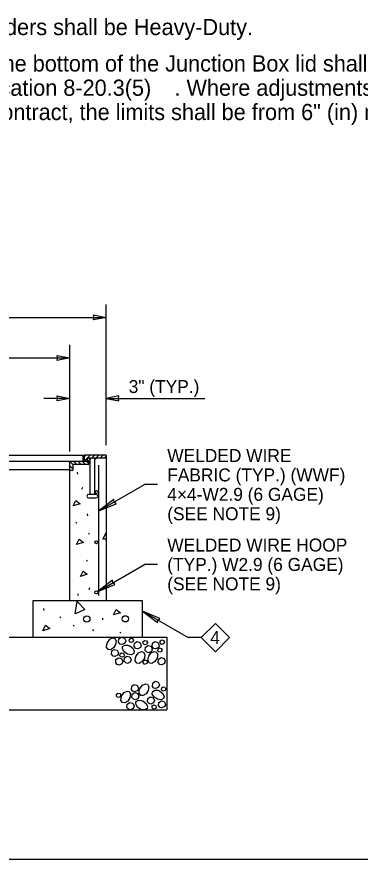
# Model space of a CAD drawing. Extents: x 99862 to 112891, y 95370 to 105076.
# Drawn here: x 102089 to 102513, y 100000 to 101040 of the extents above; entities that cross this region are included whole.
import ezdxf

# ---------------------------------------------------------------- set-up
doc = ezdxf.new("R2010")
doc.units = 0
for name, color, linetype in [('Level 1', 7, 'Continuous'), ('Level 10', 7, 'Continuous'), ('Level 12', 7, 'Continuous'), ('Level 15', 7, 'Continuous'), ('Level 2', 7, 'Continuous'), ('Level 20', 7, 'Continuous'), ('Level 3', 7, 'Continuous'), ('Level 5', 7, 'Continuous'), ('Level 6', 7, 'Continuous'), ('Level 8', 7, 'Continuous')]:
    doc.layers.add(name, color=color, linetype=linetype)

msp = doc.modelspace()

# ---------------------------------------------------------------- linework, layer by layer
at = {"layer": 'Level 1'}
for p, q in [((102199, 100498.8), (102199, 100318.8)), ((102154, 100318.8), (102154, 100480.2)), ((102244, 100318.8), (102108.6, 100318.8)), ((102108.6, 100318.8), (102108.6, 100273.8)), ((102244, 100273.8), (102244, 100318.8))]:
    msp.add_line(p, q, dxfattribs=at)
msp.add_lwpolyline([(99862, 99999.5), (103151, 99999.5), (103151, 102075.5), (99862, 102075.5)], close=True, dxfattribs=at)
at = {"layer": 'Level 10'}
msp.add_line((102190.1, 100325.2), (102190.1, 100486.4), dxfattribs=at)
for centre, radius in [((102187.2, 100453), 1.88), ((102187, 100391.1), 1.88), ((102186.9, 100329.2), 1.88), ((102175.1, 100296.3), 3.9), ((102222.7, 100296.4), 3.9)]:
    msp.add_circle(centre, radius, dxfattribs=at)
at = {"layer": 'Level 12'}
for p, q in [((102163.3, 100477.7), (102163.6, 100475.3)), ((102169.1, 100456.8), (102170.2, 100459.2)), ((102175.7, 100426.2), (102176, 100423.8)), ((102161.7, 100416), (102162.7, 100414.4)), ((102177, 100402.6), (102178.1, 100401)), ((102174.6, 100369.3), (102175.6, 100367.7)), ((102177.8, 100332.7), (102178.9, 100335)), ((102163.9, 100327.5), (102164.2, 100325.1)), ((102121.6, 100309.3), (102121.9, 100306.9)), ((102141.6, 100299.3), (102142.7, 100297.7)), ((102158.2, 100288.8), (102159.2, 100287.2)), ((102194.3, 100297.4), (102194.6, 100295)), ((102182.3, 100283.3), (102183.4, 100281.7)), ((102215.7, 100280.1), (102216.7, 100278.5)), ((102227.1, 100273.8), (102227.1, 100273.8))]:
    msp.add_line(p, q, dxfattribs=at)
for points in [[(102158.4, 100435.9), (102161.6, 100442.5), (102167, 100438.5), (102158.4, 100435.9)], [(102194.9, 100394.7), (102199, 100402.5)], [(102162.3, 100388.1), (102165.5, 100394.8), (102170.8, 100390.8), (102162.3, 100388.1)], [(102199, 100395), (102195.2, 100394.7)], [(102167.2, 100348.7), (102170.4, 100355.4), (102175.7, 100351.4), (102167.2, 100348.7)], [(102160.8, 100302.4), (102163, 100317.7)], [(102163, 100317.7), (102172.5, 100307.8), (102161.1, 100302.5)], [(102208, 100301.3), (102211.2, 100307.9), (102216.5, 100304), (102208, 100301.3)], [(102120.9, 100281.7), (102124.1, 100288.4), (102129.4, 100284.4), (102120.9, 100281.7)], [(102200.6, 100267.3), (102203.5, 100271.1), (102207.2, 100272.8), (102209.8, 100272.2), (102211.4, 100269.3), (102210.7, 100264.6), (102207.9, 100260.4), (102204.3, 100258.2), (102201.3, 100258.4), (102199.5, 100261.3), (102199.6, 100264.9), (102200.7, 100267.5)], [(102214.4, 100267.5), (102214.8, 100271.6), (102217.9, 100273.6), (102221.6, 100272.6), (102223.2, 100269.1), (102222.1, 100266.3), (102218.7, 100264.6), (102216.4, 100265.2), (102214.4, 100267.5)], [(102227.5, 100268.9), (102227.7, 100271.4), (102229.6, 100272.6), (102231.8, 100272), (102232.8, 100269.9), (102232.1, 100268.2), (102230.1, 100267.2), (102228.7, 100267.6), (102227.5, 100268.9)], [(102233.5, 100262.2), (102233.9, 100266.3), (102237.1, 100268.3), (102240.7, 100267.3), (102242.3, 100263.8), (102241.2, 100260.9), (102237.9, 100259.3), (102235.5, 100259.9), (102233.5, 100262.2)], [(102244.6, 100266), (102244.8, 100268.5), (102246.7, 100269.7), (102248.9, 100269.1), (102249.9, 100267), (102249.2, 100265.3), (102247.2, 100264.3), (102245.8, 100264.7), (102244.6, 100266)], [(102255.7, 100262.1), (102256.1, 100266.2), (102259.2, 100268.3), (102262.9, 100267.3), (102264.4, 100263.8), (102263.4, 100260.9), (102260, 100259.3), (102257.7, 100259.9), (102255.7, 100262.1)], [(102265.5, 100266.6), (102265.8, 100269.1), (102267.7, 100270.3), (102269.8, 100269.7), (102270.8, 100267.6), (102270.1, 100265.9), (102268.1, 100264.9), (102266.7, 100265.3), (102265.5, 100266.6)], [(102205.5, 100252.6), (102205.9, 100256.7), (102209, 100258.7), (102212.7, 100257.7), (102214.3, 100254.2), (102213.2, 100251.4), (102209.8, 100249.7), (102207.5, 100250.3), (102205.5, 100252.6)], [(102228.2, 100262.9), (102231.9, 100260), (102233.6, 100256.3), (102233, 100253.7), (102230.1, 100252.1), (102225.4, 100252.8), (102221.2, 100255.6), (102219, 100259.2), (102219.3, 100262.1), (102222.1, 100264), (102225.7, 100263.9), (102228.4, 100262.8)], [(102247.2, 100257.4), (102247.6, 100261.5), (102250.7, 100263.6), (102254.4, 100262.5), (102255.9, 100259), (102254.9, 100256.2), (102251.5, 100254.6), (102249.2, 100255.2), (102247.2, 100257.4)], [(102262.7, 100256.8), (102263, 100259.3), (102264.9, 100260.5), (102267, 100259.9), (102268, 100257.8), (102267.4, 100256.1), (102265.3, 100255.1), (102263.9, 100255.5), (102262.7, 100256.8)], [(102210.8, 100242.1), (102211.1, 100246.2), (102214.3, 100248.3), (102217.9, 100247.3), (102219.5, 100243.8), (102218.5, 100240.9), (102215.1, 100239.3), (102212.7, 100239.9), (102210.8, 100242.1)], [(102216, 100250.7), (102216.2, 100253.1), (102218.1, 100254.4), (102220.3, 100253.8), (102221.2, 100251.7), (102220.6, 100249.9), (102218.6, 100249), (102217.2, 100249.3), (102216, 100250.7)], [(102221.1, 100244.2), (102221.5, 100248.3), (102224.6, 100250.4), (102228.3, 100249.4), (102229.8, 100245.9), (102228.8, 100243), (102225.4, 100241.4), (102223.1, 100242), (102221.1, 100244.2)], [(102235.9, 100250.5), (102238.9, 100254.3), (102242.6, 100256), (102245.2, 100255.4), (102246.8, 100252.5), (102246.1, 100247.8), (102243.3, 100243.6), (102239.7, 100241.4), (102236.7, 100241.6), (102234.8, 100244.5), (102235, 100248.1), (102236, 100250.7)], [(102251.8, 100250.6), (102254.7, 100254.3), (102258.4, 100256), (102261, 100255.4), (102262.6, 100252.5), (102261.9, 100247.8), (102259.2, 100243.6), (102255.5, 100241.4), (102252.6, 100241.6), (102250.7, 100244.5), (102250.8, 100248.1), (102251.9, 100250.7)], [(102263.2, 100242.3), (102263.6, 100246.4), (102266.7, 100248.5), (102270.4, 100247.5), (102271.9, 100244), (102270.9, 100241.1), (102267.5, 100239.5), (102265.2, 100240.1), (102263.2, 100242.3)], [(102244.6, 100241.9), (102244.8, 100244.3), (102246.7, 100245.6), (102248.9, 100244.9), (102249.9, 100242.9), (102249.2, 100241.1), (102247.2, 100240.2), (102245.8, 100240.5), (102244.6, 100241.9)], [(102230.2, 100209.1), (102230.6, 100213.2), (102233.7, 100215.3), (102237.3, 100214.3), (102238.9, 100210.8), (102237.9, 100207.9), (102234.5, 100206.3), (102232.1, 100206.9), (102230.2, 100209.1)], [(102240.9, 100210.7), (102243.8, 100214.4), (102247.5, 100216.1), (102250.1, 100215.5), (102251.7, 100212.6), (102251, 100207.9), (102248.2, 100203.7), (102244.6, 100201.5), (102241.6, 100201.8), (102239.8, 100204.6), (102239.9, 100208.2), (102241, 100210.9)], [(102256, 100213), (102256.4, 100217.1), (102259.5, 100219.2), (102263.2, 100218.2), (102264.7, 100214.7), (102263.7, 100211.8), (102260.3, 100210.2), (102258, 100210.8), (102256, 100213)], [(102218.3, 100201.8), (102221.2, 100205.5), (102224.9, 100207.2), (102227.5, 100206.6), (102229.1, 100203.7), (102228.4, 100199), (102225.7, 100194.8), (102222, 100192.6), (102219.1, 100192.9), (102217.2, 100195.7), (102217.3, 100199.3), (102218.4, 100202)], [(102230.8, 100199.2), (102231.1, 100203.3), (102234.3, 100205.4), (102237.9, 100204.3), (102239.5, 100200.9), (102238.5, 100198), (102235.1, 100196.4), (102232.7, 100197), (102230.8, 100199.2)], [(102265.1, 100207.2), (102268.8, 100204.2), (102270.5, 100200.5), (102269.9, 100198), (102267, 100196.4), (102262.3, 100197), (102258.1, 100199.8), (102255.9, 100203.5), (102256.2, 100206.4), (102259, 100208.3), (102262.6, 100208.1), (102265.3, 100207.1)], [(102267.3, 100208.7), (102267.5, 100211.2), (102269.4, 100212.4), (102271.6, 100211.8), (102272.5, 100209.7), (102271.9, 100208), (102269.9, 100207), (102268.4, 100207.3), (102267.3, 100208.7)], [(102211.7, 100201), (102211.9, 100203.4), (102213.8, 100204.7), (102216, 100204), (102216.9, 100201.9), (102216.3, 100200.2), (102214.3, 100199.2), (102212.8, 100199.6), (102211.7, 100201)], [(102244.5, 100194.7), (102248.3, 100191.7), (102250, 100188), (102249.4, 100185.5), (102246.5, 100183.9), (102241.8, 100184.5), (102237.6, 100187.3), (102235.4, 100191), (102235.6, 100193.9), (102238.5, 100195.8), (102242.1, 100195.6), (102244.7, 100194.6)], [(102249.9, 100193.9), (102250.3, 100198), (102253.4, 100200.1), (102257.1, 100199), (102258.6, 100195.5), (102257.6, 100192.7), (102254.2, 100191.1), (102251.9, 100191.7), (102249.9, 100193.9)], [(102263.6, 100189.2), (102263.9, 100193.2), (102267.1, 100195.3), (102270.7, 100194.3), (102272.3, 100190.8), (102271.3, 100187.9), (102267.9, 100186.3), (102265.5, 100186.9), (102263.6, 100189.2)], [(102224.6, 100187), (102225, 100191.1), (102228.1, 100193.2), (102231.8, 100192.1), (102233.4, 100188.6), (102232.3, 100185.8), (102228.9, 100184.1), (102226.6, 100184.7), (102224.6, 100187)], [(102255.7, 100186.5), (102255.9, 100188.9), (102257.8, 100190.2), (102260, 100189.5), (102260.9, 100187.5), (102260.3, 100185.7), (102258.3, 100184.8), (102256.9, 100185.1), (102255.7, 100186.5)]]:
    msp.add_lwpolyline(points, dxfattribs=at)
at = {"layer": 'Level 15'}
for p, q in [((102199, 100510.8), (102199, 100684.8)), ((101659, 100668.8), (102199, 100668.8)), ((102154, 100503.3), (102154, 100634.8)), ((101704, 100618.8), (102154, 100618.8)), ((102154, 100568.8), (102122.1, 100568.8)), ((102199, 100568.8), (102320.6, 100568.8)), ((102190.1, 100429.7), (102246.4, 100462.2)), ((102262.4, 100462.2), (102246.4, 100462.2)), ((102188.5, 100330.1), (102246.4, 100363.6)), ((102262.4, 100363.6), (102246.4, 100363.6)), ((102244, 100305.7), (102300.3, 100273.2)), ((102316.3, 100273.2), (102300.3, 100273.2))]:
    msp.add_line(p, q, dxfattribs=at)
for points in [[(102199, 100668.8), (102183.3, 100665.7), (102184, 100668.8), (102183.3, 100671.9)], [(102154, 100618.8), (102138.3, 100615.7), (102139, 100618.8), (102138.3, 100621.9)], [(102154, 100568.8), (102138.3, 100565.7), (102139, 100568.8), (102138.3, 100571.9)], [(102199, 100568.8), (102214.7, 100565.7), (102214, 100568.8), (102214.7, 100571.9)], [(102190.1, 100429.7), (102211.4, 100438.5), (102208.9, 100440.6), (102208.4, 100443.7)], [(102188.5, 100330.1), (102209.8, 100339), (102207.4, 100341), (102206.8, 100344.1)], [(102244, 100305.7), (102262.3, 100291.7), (102262.9, 100294.8), (102265.3, 100296.8)]]:
    msp.add_lwpolyline(points, close=True, dxfattribs=at)
at = {"layer": 'Level 2'}
for p, q in [((102199, 100498.8), (102171.8, 100498.8)), ((102171.8, 100498.8), (102171.8, 100491.3)), ((102171.8, 100496.7), (102173.9, 100498.8)), ((102171.8, 100491.4), (102179.2, 100498.8)), ((102180.8, 100495.1), (102184.5, 100498.8)), ((102186.1, 100495.1), (102189.8, 100498.8)), ((102191.4, 100495.1), (102195.1, 100498.8)), ((102196.7, 100495.1), (102199, 100497.4)), ((102154, 100480.2), (102154, 100491.3)), ((102154, 100491.3), (102177.5, 100491.3)), ((102154, 100490.8), (102157.8, 100487)), ((102157.8, 100487.6), (102177.5, 100487.6)), ((102157.8, 100487.6), (102157.8, 100480.2)), ((102158.8, 100491.3), (102162.5, 100487.6)), ((102164.1, 100491.3), (102167.8, 100487.6)), ((102169.4, 100491.3), (102173.2, 100487.6)), ((102174.7, 100491.3), (102177.5, 100488.6)), ((102199, 100495.1), (102175.6, 100495.1)), ((102175.6, 100495.1), (102175.6, 100491.3)), ((102177.5, 100491.3), (102177.5, 100487.6)), ((102154, 100480.3), (101796.4, 100480.3)), ((102154, 100485.5), (102157.8, 100481.7)), ((102154, 100480.2), (102157.8, 100480.2))]:
    msp.add_line(p, q, dxfattribs=at)
at = {"layer": 'Level 20'}
msp.add_lwpolyline([(102333.9, 100290.7), (102351.4, 100273.2), (102333.9, 100255.6), (102316.3, 100273.2)], close=True, dxfattribs=at)
at = {"layer": 'Level 3'}
for p, q in [((101812.3, 100498.8), (102170, 100498.8)), ((102170, 100498.8), (102170, 100491.3)), ((101815.1, 100491.3), (102154, 100491.3))]:
    msp.add_line(p, q, dxfattribs=at)
at = {"layer": 'Level 5'}
for p, q in [((102179.1, 100450.1), (102179.1, 100495.1)), ((102184.7, 100495.1), (102184.7, 100450.1)), ((101584, 100273.8), (102274, 100273.8)), ((102274, 100273.8), (102274, 100183.8)), ((101584, 100183.8), (102274, 100183.8))]:
    msp.add_line(p, q, dxfattribs=at)
for points in [[(102186.4, 100450.1), (102177.4, 100450.1)], [(102177.4, 100445.8), (102186.4, 100445.8)]]:
    msp.add_lwpolyline(points, dxfattribs=at)
for centre, start, end in [((102177.4, 100447.9), 90, 180), ((102177.4, 100447.9), 180, 270), ((102186.4, 100447.9), 0, 90), ((102186.4, 100447.9), 270, 0)]:
    msp.add_arc(centre, 2.13, start, end, dxfattribs=at)
at = {"layer": 'Level 6'}
msp.add_line((102177.4, 100491.3), (102177.5, 100491.2), dxfattribs=at)
at = {"layer": 'Level 8'}
for points in [[(102177.5, 100491.3), (102175.6, 100491.3), (102175.6, 100493.2)], [(102177.2, 100495.1), (102179.1, 100495.1), (102179.1, 100493.2)], [(102186.6, 100495.1), (102184.7, 100495.1), (102184.7, 100493.2)]]:
    msp.add_lwpolyline(points, close=True, dxfattribs=at)

# ---------------------------------------------------------------- texts
at = {"layer": 'Level 20'}
for s, height, p in [('placed within the traveled way or paved shoulders shall be Heavy-Duty.', 20, (101534.4, 101017.6)), ('Distance between the top of the conduit and the bottom of the Junction Box lid shall be 6" (in) min. to 8" (in) max. for final grade of ', 20, (101534.4, 100972.6)), (' Standard Specification 8-20.3(5)', 20, (101863.6, 100942.6)), ('. Where adjustments are to be made to existing Junction Boxes, ', 20, (102283.3, 100942.6)), ('or for interim construction stages during the contract, the limits shall be from 6" (in) min. to 10" (in) max. See', 20, (101534.4, 100912.6)), ('3" (TYP.)', 16, (102226.8, 100575.4)), ('WELDED WIRE', 16, (102274.4, 100490.2)), ('FABRIC (TYP.) (WWF) ', 16, (102274.4, 100466.2)), ('4×4-W2.9 (6 GAGE)', 16, (102274.4, 100442.2)), ('(SEE NOTE 9)', 16, (102274.4, 100418.2)), ('WELDED WIRE HOOP', 16, (102274.4, 100379.6)), ('(TYP.) W2.9 (6 GAGE) ', 16, (102274.4, 100355.6)), ('(SEE NOTE 9)', 16, (102274.4, 100331.6)), ('4', 16, (102327.4, 100265.2))]:
    msp.add_text(s, height=height, dxfattribs=at).set_placement(p)

doc.saveas('drawing.dxf')
